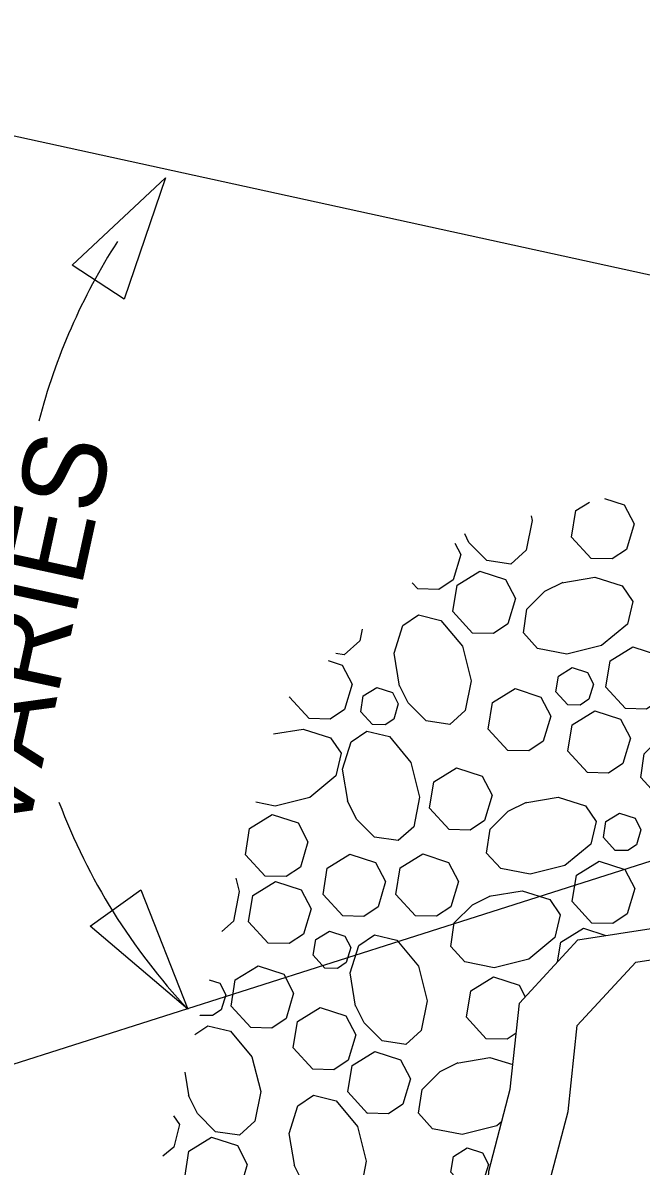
# Model space of a CAD drawing. Extents: x 2126110 to 2128246, y 1804858 to 1811658.
# Drawn here: x 2126424.9 to 2126574.3, y 1809484.3 to 1809760.3 of the extents above; entities that cross this region are included whole.
import ezdxf

# ---------------------------------------------------------------- set-up
doc = ezdxf.new("R2010")
doc.units = 0
for name, color, linetype in [('1', 7, 'Continuous'), ('DET-EARTH', 7, 'Continuous'), ('Old_Level_1', 7, 'Continuous'), ('Old_Level_41', 7, 'Continuous')]:
    doc.layers.add(name, color=color, linetype=linetype)

msp = doc.modelspace()

# ---------------------------------------------------------------- linework, layer by layer
at = {"layer": '1'}
msp.add_line((2126764.58, 1809658.28), (2126297.5, 1809760.34), dxfattribs=at)
for points in [[(2126436.8, 1809701.8), (2126459.4, 1809722.91), (2126449.39, 1809693.65)], [(2126453.41, 1809550.97), (2126464.74, 1809522.2), (2126441.2, 1809542.25)]]:
    msp.add_lwpolyline(points, close=True, dxfattribs=at)
at = {"layer": 'DET-EARTH'}
msp.add_line((2126390, 1809498.52), (2126846.51, 1809643.98), dxfattribs=at)
for points in [[(2126537.44, 1809483.07), (2126542.6, 1809502.83), (2126544.85, 1809523.64), (2126558.97, 1809538.93), (2126587.62, 1809543.35), (2126607.62, 1809532.1), (2126609.14, 1809515.53), (2126606.45, 1809502.52), (2126600.58, 1809471.68), (2126594.2, 1809463.53), (2126574.53, 1809458.04), (2126574.53, 1809458.04), (2126548.48, 1809457.82), (2126536.92, 1809472.63), (2126537.44, 1809483.07)], [(2126551.42, 1809477.69), (2126556.59, 1809497.45), (2126558.83, 1809518.25), (2126572.95, 1809533.55), (2126601.6, 1809537.96), (2126617.76, 1809526.03), (2126623.12, 1809510.15), (2126620.43, 1809497.14), (2126614.56, 1809466.3), (2126608.18, 1809458.15), (2126588.51, 1809452.65), (2126588.51, 1809452.65), (2126562.46, 1809452.43), (2126550.9, 1809467.25), (2126551.42, 1809477.69)]]:
    msp.add_lwpolyline(points, dxfattribs=at)
for start, end in [(147.3917, 165.3485), (200.7072, 223.0866)]:
    msp.add_arc((2126575.51, 1809625.81), 151.68, start, end, dxfattribs=at)
at = {"layer": 'Old_Level_1'}
for p, q in [((2126520.31, 1809623.66), (2126518.93, 1809625.16)), ((2126467.7, 1809520.68), (2126467.68, 1809520.7)), ((2126465.07, 1809500.97), (2126464.08, 1809506.98))]:
    msp.add_line(p, q, dxfattribs=at)
for points in [[(2126562.18, 1809631.02), (2126557.44, 1809636.18), (2126558.45, 1809642.55), (2126561.75, 1809644.59)], [(2126565.44, 1809645.45), (2126570.16, 1809643.92), (2126572.54, 1809639.33), (2126570.74, 1809633.21), (2126567.26, 1809630.91), (2126562.18, 1809631.02)], [(2126547.65, 1809641.27), (2126547.93, 1809640.18), (2126546.5, 1809633.03), (2126542.78, 1809629.65), (2126537.02, 1809630.51), (2126532.67, 1809634.87), (2126531.63, 1809636.97)], [(2126529.23, 1809634.73), (2126530.67, 1809631.96), (2126528.86, 1809625.85), (2126525.39, 1809623.54), (2126520.31, 1809623.66)], [(2126533.52, 1809613), (2126528.77, 1809618.17), (2126529.79, 1809624.54), (2126535.28, 1809627.92), (2126541.5, 1809625.9), (2126543.88, 1809621.31), (2126542.07, 1809615.19), (2126538.6, 1809612.89), (2126533.52, 1809613)], [(2126555.06, 1809625.16), (2126563.07, 1809626.47), (2126569.71, 1809624.41), (2126572.26, 1809620.64), (2126570.96, 1809615.17), (2126564.71, 1809609.99), (2126556.34, 1809607.87), (2126549.19, 1809609.3), (2126545.81, 1809613.02), (2126546.67, 1809618.77), (2126551.03, 1809623.13), (2126555.4, 1809625.28)], [(2126515.92, 1809600.15), (2126514.61, 1809608.16), (2126516.68, 1809614.81), (2126520.44, 1809617.36), (2126525.91, 1809616.05), (2126531.09, 1809609.8), (2126533.22, 1809601.43), (2126531.78, 1809594.29), (2126528.06, 1809590.91), (2126522.31, 1809591.76), (2126517.95, 1809596.12), (2126515.8, 1809600.49)], [(2126506.84, 1809613.92), (2126506.27, 1809611.09), (2126502.55, 1809607.71), (2126500.49, 1809608.02)], [(2126570.49, 1809594.74), (2126565.75, 1809599.9), (2126566.76, 1809606.27), (2126572.25, 1809609.66), (2126578.47, 1809607.63), (2126580.85, 1809603.04), (2126579.04, 1809596.93), (2126575.57, 1809594.62), (2126570.49, 1809594.74)], [(2126498.68, 1809606.34), (2126502.07, 1809605.24), (2126504.45, 1809600.65), (2126502.64, 1809594.53), (2126499.17, 1809592.23), (2126494.09, 1809592.35)], [(2126556.51, 1809595.69), (2126553.66, 1809598.79), (2126554.27, 1809602.61), (2126557.56, 1809604.64), (2126561.29, 1809603.43), (2126562.72, 1809600.67), (2126561.64, 1809597), (2126559.55, 1809595.62), (2126556.51, 1809595.69)], [(2126509.38, 1809590.88), (2126506.53, 1809593.98), (2126507.14, 1809597.81), (2126510.43, 1809599.83), (2126514.16, 1809598.62), (2126515.59, 1809595.87), (2126514.51, 1809592.2), (2126512.42, 1809590.82), (2126509.38, 1809590.89)], [(2126542.06, 1809584.66), (2126537.32, 1809589.82), (2126538.33, 1809596.19), (2126543.82, 1809599.58), (2126550.04, 1809597.55), (2126552.42, 1809592.96), (2126550.62, 1809586.85), (2126547.14, 1809584.54), (2126542.06, 1809584.66)], [(2126494.09, 1809592.34), (2126489.34, 1809597.51), (2126489.37, 1809597.68)], [(2126561.28, 1809579.3), (2126556.54, 1809584.47), (2126557.56, 1809590.84), (2126563.05, 1809594.22), (2126569.26, 1809592.2), (2126571.65, 1809587.6), (2126569.84, 1809581.49), (2126566.37, 1809579.19), (2126561.29, 1809579.3)], [(2126583.4, 1809590.24), (2126591.41, 1809591.56), (2126598.05, 1809589.49), (2126600.6, 1809585.73), (2126599.3, 1809580.25), (2126593.05, 1809575.08), (2126584.67, 1809572.95), (2126577.53, 1809574.38), (2126574.15, 1809578.1), (2126575.01, 1809583.85), (2126579.36, 1809588.21), (2126583.74, 1809590.37)], [(2126485.48, 1809588.62), (2126492.59, 1809589.79), (2126499.24, 1809587.72), (2126501.79, 1809583.96), (2126500.48, 1809578.48), (2126494.23, 1809573.31), (2126485.86, 1809571.18), (2126481.16, 1809572.12)], [(2126503.45, 1809572.1), (2126502.14, 1809580.12), (2126504.21, 1809586.76), (2126507.97, 1809589.31), (2126513.44, 1809588.01), (2126518.62, 1809581.76), (2126520.75, 1809573.38), (2126519.31, 1809566.24), (2126515.59, 1809562.86), (2126509.84, 1809563.72), (2126505.48, 1809568.07), (2126503.33, 1809572.44)], [(2126527.89, 1809565.52), (2126523.15, 1809570.68), (2126524.16, 1809577.05), (2126529.65, 1809580.43), (2126535.87, 1809578.41), (2126538.25, 1809573.82), (2126536.44, 1809567.71), (2126532.97, 1809565.41), (2126527.89, 1809565.52)], [(2126546.19, 1809572.01), (2126554.2, 1809573.33), (2126560.85, 1809571.26), (2126563.4, 1809567.5), (2126562.09, 1809562.03), (2126555.84, 1809556.85), (2126547.47, 1809554.73), (2126540.33, 1809556.15), (2126536.94, 1809559.88), (2126537.8, 1809565.62), (2126542.16, 1809569.98), (2126546.53, 1809572.14)], [(2126483.4, 1809554.28), (2126478.66, 1809559.45), (2126479.67, 1809565.82), (2126485.16, 1809569.2), (2126491.38, 1809567.18), (2126493.76, 1809562.59), (2126491.95, 1809556.47), (2126488.48, 1809554.17), (2126483.4, 1809554.29)], [(2126567.99, 1809560.52), (2126565.14, 1809563.62), (2126565.75, 1809567.45), (2126569.05, 1809569.47), (2126572.77, 1809568.26), (2126574.2, 1809565.51), (2126573.12, 1809561.84), (2126571.04, 1809560.45), (2126567.99, 1809560.52)], [(2126502.16, 1809544.68), (2126497.41, 1809549.85), (2126498.43, 1809556.22), (2126503.92, 1809559.6), (2126510.13, 1809557.58), (2126512.52, 1809552.99), (2126510.71, 1809546.87), (2126507.24, 1809544.57), (2126502.16, 1809544.69)], [(2126519.75, 1809544.72), (2126515, 1809549.89), (2126516.02, 1809556.26), (2126521.51, 1809559.64), (2126527.73, 1809557.62), (2126530.11, 1809553.03), (2126528.3, 1809546.91), (2126524.83, 1809544.61), (2126519.75, 1809544.73)], [(2126562.34, 1809542.97), (2126557.59, 1809548.13), (2126558.61, 1809554.51), (2126564.1, 1809557.89), (2126570.32, 1809555.87), (2126572.7, 1809551.27), (2126570.89, 1809545.16), (2126567.42, 1809542.86), (2126562.34, 1809542.97)], [(2126476.36, 1809553.83), (2126477.19, 1809550.58), (2126475.76, 1809543.44), (2126472.98, 1809540.91)], [(2126484.17, 1809538.1), (2126479.43, 1809543.27), (2126480.44, 1809549.64), (2126485.93, 1809553.02), (2126492.15, 1809551), (2126494.53, 1809546.41), (2126492.73, 1809540.29), (2126489.25, 1809537.99), (2126484.18, 1809538.11)], [(2126537.51, 1809549.43), (2126545.52, 1809550.75), (2126552.17, 1809548.68), (2126554.72, 1809544.92), (2126553.41, 1809539.44), (2126547.16, 1809534.27), (2126538.79, 1809532.14), (2126531.65, 1809533.57), (2126528.26, 1809537.29), (2126529.12, 1809543.04), (2126533.48, 1809547.4), (2126537.85, 1809549.56)], [(2126497.88, 1809532.08), (2126495.04, 1809535.18), (2126495.64, 1809539.01), (2126498.94, 1809541.04), (2126502.67, 1809539.82), (2126504.1, 1809537.07), (2126503.01, 1809533.4), (2126500.93, 1809532.02), (2126497.88, 1809532.09)], [(2126554.07, 1809533.63), (2126554.83, 1809538.35), (2126560.32, 1809541.73), (2126565.72, 1809539.97)], [(2126505.29, 1809522.91), (2126503.98, 1809530.92), (2126506.04, 1809537.57), (2126509.81, 1809540.12), (2126515.28, 1809538.82), (2126520.46, 1809532.57), (2126522.58, 1809524.19), (2126521.15, 1809517.05), (2126517.43, 1809513.67), (2126511.68, 1809514.53), (2126507.32, 1809518.88), (2126505.17, 1809523.25)], [(2126479.96, 1809517.72), (2126475.22, 1809522.89), (2126476.23, 1809529.26), (2126481.72, 1809532.64), (2126487.94, 1809530.62), (2126490.32, 1809526.02), (2126488.51, 1809519.91), (2126485.04, 1809517.61), (2126479.96, 1809517.73)], [(2126536.84, 1809515.03), (2126532.09, 1809520.2), (2126533.11, 1809526.57), (2126538.6, 1809529.95), (2126544.81, 1809527.93), (2126546.25, 1809525.16)], [(2126469.92, 1809529.25), (2126472.49, 1809528.42), (2126473.92, 1809525.66), (2126472.83, 1809521.99), (2126470.75, 1809520.61), (2126467.7, 1809520.68)], [(2126494.96, 1809507.67), (2126490.22, 1809512.84), (2126491.23, 1809519.21), (2126496.72, 1809522.59), (2126502.94, 1809520.57), (2126505.32, 1809515.98), (2126503.52, 1809509.86), (2126500.04, 1809507.56), (2126494.96, 1809507.67)], [(2126466.46, 1809516.06), (2126469.58, 1809518.18), (2126475.06, 1809516.87), (2126480.23, 1809510.62), (2126482.36, 1809502.25), (2126480.93, 1809495.11), (2126477.21, 1809491.72), (2126471.46, 1809492.58), (2126467.1, 1809496.94), (2126464.94, 1809501.31)], [(2126544.06, 1809516.34), (2126541.92, 1809514.92), (2126536.84, 1809515.04)], [(2126508.17, 1809497.01), (2126503.43, 1809502.18), (2126504.44, 1809508.55), (2126509.93, 1809511.93), (2126516.15, 1809509.91), (2126518.53, 1809505.32), (2126516.72, 1809499.21), (2126513.25, 1809496.9), (2126508.17, 1809497.02)], [(2126540.56, 1809495), (2126539.37, 1809494.01), (2126530.99, 1809491.88), (2126523.85, 1809493.31), (2126520.47, 1809497.03), (2126521.33, 1809502.78), (2126525.68, 1809507.14), (2126530.05, 1809509.3)], [(2126529.71, 1809509.17), (2126537.72, 1809510.49), (2126543.25, 1809508.77)], [(2126490.58, 1809484.17), (2126489.27, 1809492.18), (2126491.33, 1809498.82), (2126495.09, 1809501.37), (2126500.57, 1809500.07), (2126505.75, 1809493.82), (2126507.87, 1809485.45), (2126506.44, 1809478.3), (2126502.72, 1809474.92), (2126496.97, 1809475.78), (2126492.61, 1809480.14), (2126490.45, 1809484.51)], [(2126461.31, 1809496.41), (2126462.72, 1809494.33), (2126461.41, 1809488.86), (2126458.76, 1809486.66)], [(2126468.74, 1809476.36), (2126464, 1809481.52), (2126465.02, 1809487.89), (2126470.51, 1809491.28), (2126476.72, 1809489.26), (2126479.1, 1809484.66), (2126477.3, 1809478.55), (2126473.83, 1809476.24), (2126468.75, 1809476.36)], [(2126531.16, 1809479.7), (2126528.31, 1809482.8), (2126528.92, 1809486.62), (2126532.22, 1809488.65), (2126535.95, 1809487.44), (2126537.38, 1809484.68), (2126536.29, 1809481.02), (2126534.21, 1809479.64), (2126531.16, 1809479.71)]]:
    msp.add_lwpolyline(points, dxfattribs=at)
at = {"layer": 'Old_Level_41'}
msp.add_lwpolyline([(2126537.44, 1809483.07), (2126542.6, 1809502.83), (2126544.85, 1809523.64), (2126558.97, 1809538.93), (2126587.62, 1809543.35), (2126607.62, 1809532.1), (2126609.14, 1809515.53), (2126606.45, 1809502.52), (2126600.58, 1809471.68), (2126594.2, 1809463.53), (2126574.53, 1809458.04), (2126574.53, 1809458.04), (2126548.48, 1809457.82), (2126536.92, 1809472.63), (2126537.44, 1809483.07)], dxfattribs=at)

# ---------------------------------------------------------------- texts
at = {"layer": 'DET-EARTH'}
msp.add_text('VARIES', height=20, rotation=77.6736, dxfattribs=at).set_placement((2126425.65, 1809562.73))

doc.saveas('drawing.dxf')
